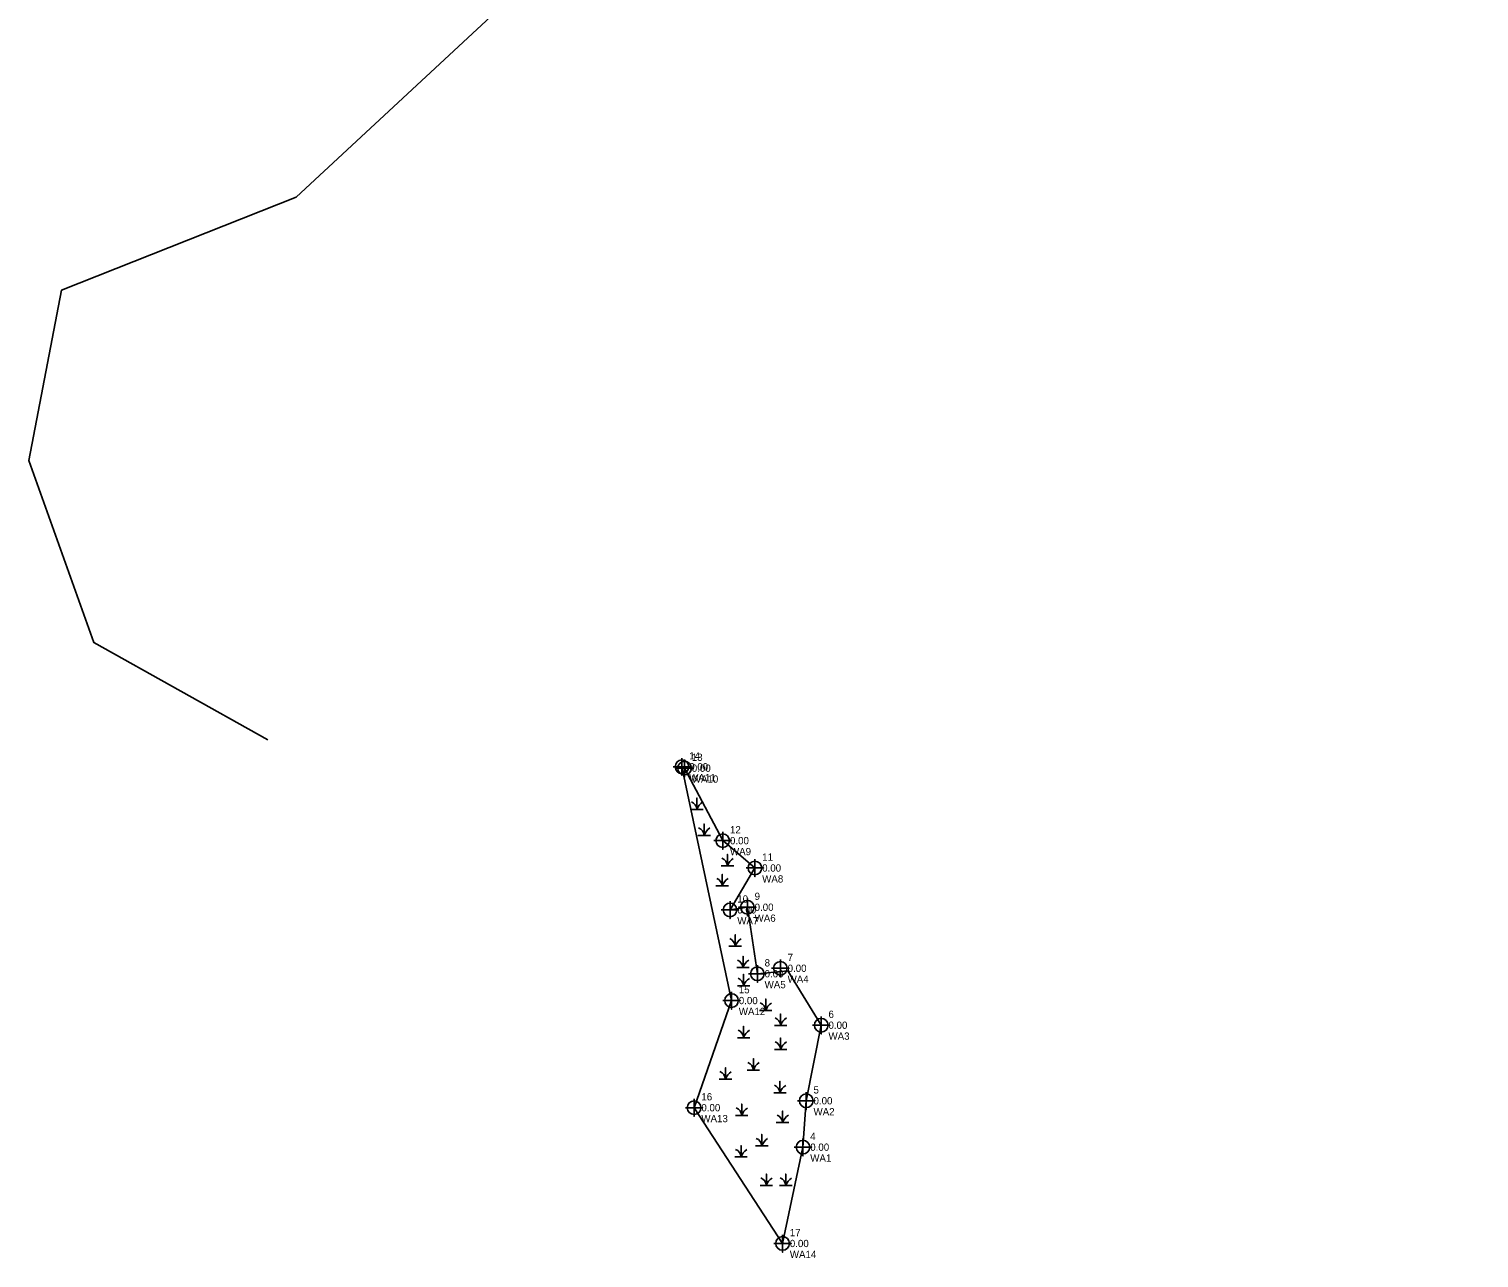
# Model space of a CAD drawing. Extents: x 2144593 to 2145092, y 864685 to 865530.
import ezdxf

# ---------------------------------------------------------------- set-up
doc = ezdxf.new("R2010")
doc.units = 0
for name, color, linetype in [('Exist Environmental Wetland Boundary', 7, 'Continuous'), ('Exist Environmental Wetland Boundary Cogo Comment', 7, 'Continuous'), ('Exist Environmental Wetland Boundary Cogo Elevation', 7, 'Continuous'), ('Exist Environmental Wetland Boundary Cogo Number', 7, 'Continuous'), ('Exist Environmental Wetland Boundary Cogo Point CELL', 7, 'Continuous'), ('Exist Hydro Jurisdictional Stream or Body of Water NEU Mitigable', 7, 'Continuous'), ('Exist Hydro Swamp or Marsh', 7, 'Continuous')]:
    doc.layers.add(name, color=color, linetype=linetype)

msp = doc.modelspace()

# ---------------------------------------------------------------- linework, layer by layer
at = {"layer": 'Exist Environmental Wetland Boundary'}
msp.add_lwpolyline([(2144834.78, 864773.53), (2144821.91, 864736.68), (2144852.33, 864689.99), (2144859.35, 864723.11), (2144860.47, 864739.06), (2144865.62, 864765.05), (2144854.17, 864783.76), (2144843.66, 864782.75), (2144840.22, 864805.62), (2144834.26, 864804.71), (2144842.82, 864819.12), (2144831.75, 864828.52), (2144818.62, 864853.45), (2144817.73, 864853.93)], close=True, dxfattribs=at)
at = {"layer": 'Exist Environmental Wetland Boundary Cogo Point CELL'}
for points in [[(2144817.73, 864856.93), (2144817.73, 864850.93), (2144817.73, 864853.93), (2144820.73, 864853.93), (2144814.73, 864853.93)], [(2144818.62, 864856.45), (2144818.62, 864850.45), (2144818.62, 864853.45), (2144821.62, 864853.45), (2144815.62, 864853.45)], [(2144831.75, 864831.52), (2144831.75, 864825.52), (2144831.75, 864828.52), (2144834.75, 864828.52), (2144828.75, 864828.52)], [(2144842.82, 864822.12), (2144842.82, 864816.12), (2144842.82, 864819.12), (2144845.82, 864819.12), (2144839.82, 864819.12)], [(2144834.26, 864807.71), (2144834.26, 864801.71), (2144834.26, 864804.71), (2144837.26, 864804.71), (2144831.26, 864804.71)], [(2144840.22, 864808.62), (2144840.22, 864802.62), (2144840.22, 864805.62), (2144843.22, 864805.62), (2144837.22, 864805.62)], [(2144843.66, 864785.75), (2144843.66, 864779.75), (2144843.66, 864782.75), (2144846.66, 864782.75), (2144840.66, 864782.75)], [(2144851.57, 864787.63), (2144851.57, 864781.63), (2144851.57, 864784.63), (2144854.57, 864784.63), (2144848.57, 864784.63)], [(2144834.78, 864776.53), (2144834.78, 864770.53), (2144834.78, 864773.53), (2144837.78, 864773.53), (2144831.78, 864773.53)], [(2144865.62, 864768.05), (2144865.62, 864762.05), (2144865.62, 864765.05), (2144868.62, 864765.05), (2144862.62, 864765.05)], [(2144821.91, 864739.68), (2144821.91, 864733.68), (2144821.91, 864736.68), (2144824.91, 864736.68), (2144818.91, 864736.68)], [(2144860.47, 864742.06), (2144860.47, 864736.06), (2144860.47, 864739.06), (2144863.47, 864739.06), (2144857.47, 864739.06)], [(2144859.35, 864726.11), (2144859.35, 864720.11), (2144859.35, 864723.11), (2144862.35, 864723.11), (2144856.35, 864723.11)], [(2144852.33, 864692.99), (2144852.33, 864686.99), (2144852.33, 864689.99), (2144855.33, 864689.99), (2144849.33, 864689.99)]]:
    msp.add_lwpolyline(points, dxfattribs=at)
for centre in [(2144817.73, 864853.93), (2144818.62, 864853.45), (2144831.75, 864828.52), (2144842.82, 864819.12), (2144834.26, 864804.71), (2144840.22, 864805.62), (2144843.66, 864782.75), (2144851.57, 864784.63), (2144834.78, 864773.53), (2144865.62, 864765.05), (2144860.47, 864739.06), (2144821.91, 864736.68), (2144859.35, 864723.11), (2144852.33, 864689.99)]:
    msp.add_circle(centre, 2.34, dxfattribs=at)
at = {"layer": 'Exist Hydro Jurisdictional Stream or Body of Water NEU Mitigable'}
msp.add_lwpolyline([(2145091.81, 865530.32), (2144973.43, 865452.32), (2144921.9, 865282.4), (2144862.01, 865214.16), (2144685.13, 865049.81), (2144604.35, 865017.78), (2144593.2, 864959.28), (2144615.49, 864896.61), (2144675.38, 864863.18)], dxfattribs=at)
at = {"layer": 'Exist Hydro Swamp or Marsh'}
for p, q in [((2144822.9, 864841.04), (2144822.9, 864841.04)), ((2144825.35, 864832.12), (2144825.35, 864832.12)), ((2144833.38, 864821.64), (2144833.38, 864821.64)), ((2144831.59, 864814.73), (2144831.59, 864814.73)), ((2144836.05, 864793.99), (2144836.05, 864793.99)), ((2144838.73, 864786.63), (2144838.73, 864786.63)), ((2144838.95, 864780.39), (2144838.95, 864780.39)), ((2144846.54, 864771.91), (2144846.54, 864771.91)), ((2144851.66, 864766.78), (2144851.66, 864766.78)), ((2144838.95, 864762.55), (2144838.95, 864762.55)), ((2144851.66, 864758.53), (2144851.66, 864758.53)), ((2144842.3, 864751.4), (2144842.3, 864751.4)), ((2144832.71, 864748.27), (2144832.71, 864748.27)), ((2144851.44, 864743.59), (2144851.44, 864743.59)), ((2144838.28, 864735.79), (2144838.28, 864735.79)), ((2144852.33, 864733.33), (2144852.33, 864733.33)), ((2144845.2, 864725.3), (2144845.2, 864725.3)), ((2144838.06, 864721.51), (2144838.06, 864721.51)), ((2144846.76, 864711.7), (2144846.76, 864711.7)), ((2144853.45, 864711.7), (2144853.45, 864711.7))]:
    msp.add_line(p, q, dxfattribs=at)
for points in [[(2144820.75, 864839.26), (2144822.9, 864839.26), (2144822.9, 864843.21), (2144822.9, 864839.26), (2144825.05, 864839.26)], [(2144823.2, 864830.34), (2144825.35, 864830.34), (2144825.35, 864834.29), (2144825.35, 864830.34), (2144827.5, 864830.34)], [(2144831.23, 864819.86), (2144833.38, 864819.86), (2144833.38, 864823.8), (2144833.38, 864819.86), (2144835.53, 864819.86)], [(2144829.44, 864812.95), (2144831.6, 864812.95), (2144831.6, 864816.89), (2144831.6, 864812.95), (2144833.75, 864812.95)], [(2144833.9, 864792.21), (2144836.06, 864792.21), (2144836.06, 864796.15), (2144836.06, 864792.21), (2144838.21, 864792.21)], [(2144836.58, 864784.85), (2144838.73, 864784.85), (2144838.73, 864788.79), (2144838.73, 864784.85), (2144840.88, 864784.85)], [(2144836.8, 864778.6), (2144838.95, 864778.6), (2144838.95, 864782.55), (2144838.95, 864778.6), (2144841.1, 864778.6)], [(2144844.39, 864770.13), (2144846.54, 864770.13), (2144846.54, 864774.07), (2144846.54, 864770.13), (2144848.69, 864770.13)], [(2144836.8, 864760.76), (2144838.95, 864760.76), (2144838.95, 864764.71), (2144838.95, 864760.76), (2144841.1, 864760.76)], [(2144849.52, 864765), (2144851.67, 864765), (2144851.67, 864768.95), (2144851.67, 864765), (2144853.82, 864765)], [(2144849.52, 864756.75), (2144851.67, 864756.75), (2144851.67, 864760.69), (2144851.67, 864756.75), (2144853.82, 864756.75)], [(2144830.56, 864746.49), (2144832.71, 864746.49), (2144832.71, 864750.44), (2144832.71, 864746.49), (2144834.86, 864746.49)], [(2144840.15, 864749.61), (2144842.3, 864749.61), (2144842.3, 864753.56), (2144842.3, 864749.61), (2144844.45, 864749.61)], [(2144849.29, 864741.81), (2144851.44, 864741.81), (2144851.44, 864745.75), (2144851.44, 864741.81), (2144853.59, 864741.81)], [(2144836.13, 864734), (2144838.29, 864734), (2144838.29, 864737.95), (2144838.29, 864734), (2144840.44, 864734)], [(2144850.18, 864731.55), (2144852.33, 864731.55), (2144852.33, 864735.49), (2144852.33, 864731.55), (2144854.48, 864731.55)], [(2144843.05, 864723.52), (2144845.2, 864723.52), (2144845.2, 864727.47), (2144845.2, 864723.52), (2144847.35, 864723.52)], [(2144835.91, 864719.73), (2144838.06, 864719.73), (2144838.06, 864723.68), (2144838.06, 864719.73), (2144840.21, 864719.73)], [(2144844.61, 864709.92), (2144846.76, 864709.92), (2144846.76, 864713.86), (2144846.76, 864709.92), (2144848.91, 864709.92)], [(2144851.3, 864709.92), (2144853.45, 864709.92), (2144853.45, 864713.86), (2144853.45, 864709.92), (2144855.6, 864709.92)]]:
    msp.add_lwpolyline(points, dxfattribs=at)
for centre, radius, start, end in [((2144819.83, 864839.04), 3.07, 4.1403, 67.535), ((2144827.46, 864837.75), 4.81, 122.1274, 161.6222), ((2144822.28, 864830.12), 3.07, 4.1403, 67.535), ((2144829.91, 864828.82), 4.81, 122.1274, 161.6222), ((2144830.31, 864819.64), 3.07, 4.1403, 67.535), ((2144837.94, 864818.34), 4.81, 122.1274, 161.6222), ((2144828.53, 864812.72), 3.07, 4.1403, 67.535), ((2144836.16, 864811.43), 4.81, 122.1274, 161.6222), ((2144832.99, 864791.98), 3.07, 4.1403, 67.535), ((2144840.62, 864790.69), 4.81, 122.1274, 161.6222), ((2144835.66, 864784.63), 3.07, 4.1403, 67.535), ((2144843.29, 864783.33), 4.81, 122.1274, 161.6222), ((2144835.89, 864778.38), 3.07, 4.1403, 67.535), ((2144843.51, 864777.09), 4.81, 122.1274, 161.6222), ((2144843.47, 864769.91), 3.07, 4.1403, 67.535), ((2144851.1, 864768.61), 4.81, 122.1274, 161.6222), ((2144848.6, 864764.78), 3.07, 4.1403, 67.535), ((2144856.23, 864763.48), 4.81, 122.1274, 161.6222), ((2144835.89, 864760.54), 3.07, 4.1403, 67.535), ((2144843.51, 864759.25), 4.81, 122.1274, 161.6222), ((2144848.6, 864756.53), 3.07, 4.1403, 67.535), ((2144856.23, 864755.23), 4.81, 122.1274, 161.6222), ((2144839.23, 864749.39), 3.07, 4.1403, 67.535), ((2144846.86, 864748.1), 4.81, 122.1274, 161.6222), ((2144829.64, 864746.27), 3.07, 4.1403, 67.535), ((2144837.27, 864744.98), 4.81, 122.1274, 161.6222), ((2144848.38, 864741.59), 3.07, 4.1403, 67.535), ((2144856, 864740.29), 4.81, 122.1274, 161.6222), ((2144835.22, 864733.78), 3.07, 4.1403, 67.535), ((2144842.85, 864732.49), 4.81, 122.1274, 161.6222), ((2144849.27, 864731.33), 3.07, 4.1403, 67.535), ((2144856.9, 864730.03), 4.81, 122.1274, 161.6222), ((2144842.13, 864723.3), 3.07, 4.1403, 67.535), ((2144849.76, 864722.01), 4.81, 122.1274, 161.6222), ((2144835, 864719.51), 3.07, 4.1403, 67.535), ((2144842.62, 864718.21), 4.81, 122.1274, 161.6222), ((2144843.69, 864709.7), 3.07, 4.1403, 67.535), ((2144851.32, 864708.4), 4.81, 122.1274, 161.6222), ((2144850.38, 864709.7), 3.07, 4.1403, 67.535), ((2144858.01, 864708.4), 4.81, 122.1274, 161.6222)]:
    msp.add_arc(centre, radius, start, end, dxfattribs=at)

# ---------------------------------------------------------------- texts
at = {"layer": 'Exist Environmental Wetland Boundary Cogo Comment'}
for s, p in [('WA11', (2144820.23, 864848.93)), ('WA10', (2144821.12, 864848.45)), ('WA9', (2144834.25, 864823.52)), ('WA8', (2144845.32, 864814.12)), ('WA7', (2144836.76, 864799.71)), ('WA6', (2144842.72, 864800.62)), ('WA5', (2144846.16, 864777.75)), ('WA4', (2144854.07, 864779.63)), ('WA12', (2144837.28, 864768.53)), ('WA3', (2144868.12, 864760.05)), ('WA2', (2144862.97, 864734.06)), ('WA13', (2144824.41, 864731.69)), ('WA1', (2144861.85, 864718.11)), ('WA14', (2144854.83, 864684.99))]:
    msp.add_text(s, height=2.5, dxfattribs=at).set_placement(p)
at = {"layer": 'Exist Environmental Wetland Boundary Cogo Elevation'}
for p in [(2144820.23, 864852.68), (2144821.12, 864852.2), (2144834.25, 864827.27), (2144845.32, 864817.87), (2144836.76, 864803.46), (2144842.72, 864804.37), (2144854.07, 864783.38), (2144846.16, 864781.5), (2144837.28, 864772.28), (2144868.12, 864763.8), (2144862.97, 864737.81), (2144824.41, 864735.44), (2144861.85, 864721.86), (2144854.83, 864688.74)]:
    msp.add_text('0.00', height=2.5, dxfattribs=at).set_placement(p)
at = {"layer": 'Exist Environmental Wetland Boundary Cogo Number'}
for s, p in [('14', (2144820.23, 864856.43)), ('13', (2144821.12, 864855.95)), ('12', (2144834.25, 864831.02)), ('11', (2144845.32, 864821.62)), ('10', (2144836.76, 864807.21)), ('9', (2144842.72, 864808.12)), ('7', (2144854.07, 864787.13)), ('8', (2144846.16, 864785.25)), ('15', (2144837.28, 864776.03)), ('6', (2144868.12, 864767.55)), ('16', (2144824.41, 864739.19)), ('5', (2144862.97, 864741.56)), ('4', (2144861.85, 864725.61)), ('17', (2144854.83, 864692.49))]:
    msp.add_text(s, height=2.5, dxfattribs=at).set_placement(p)

doc.saveas('drawing.dxf')
